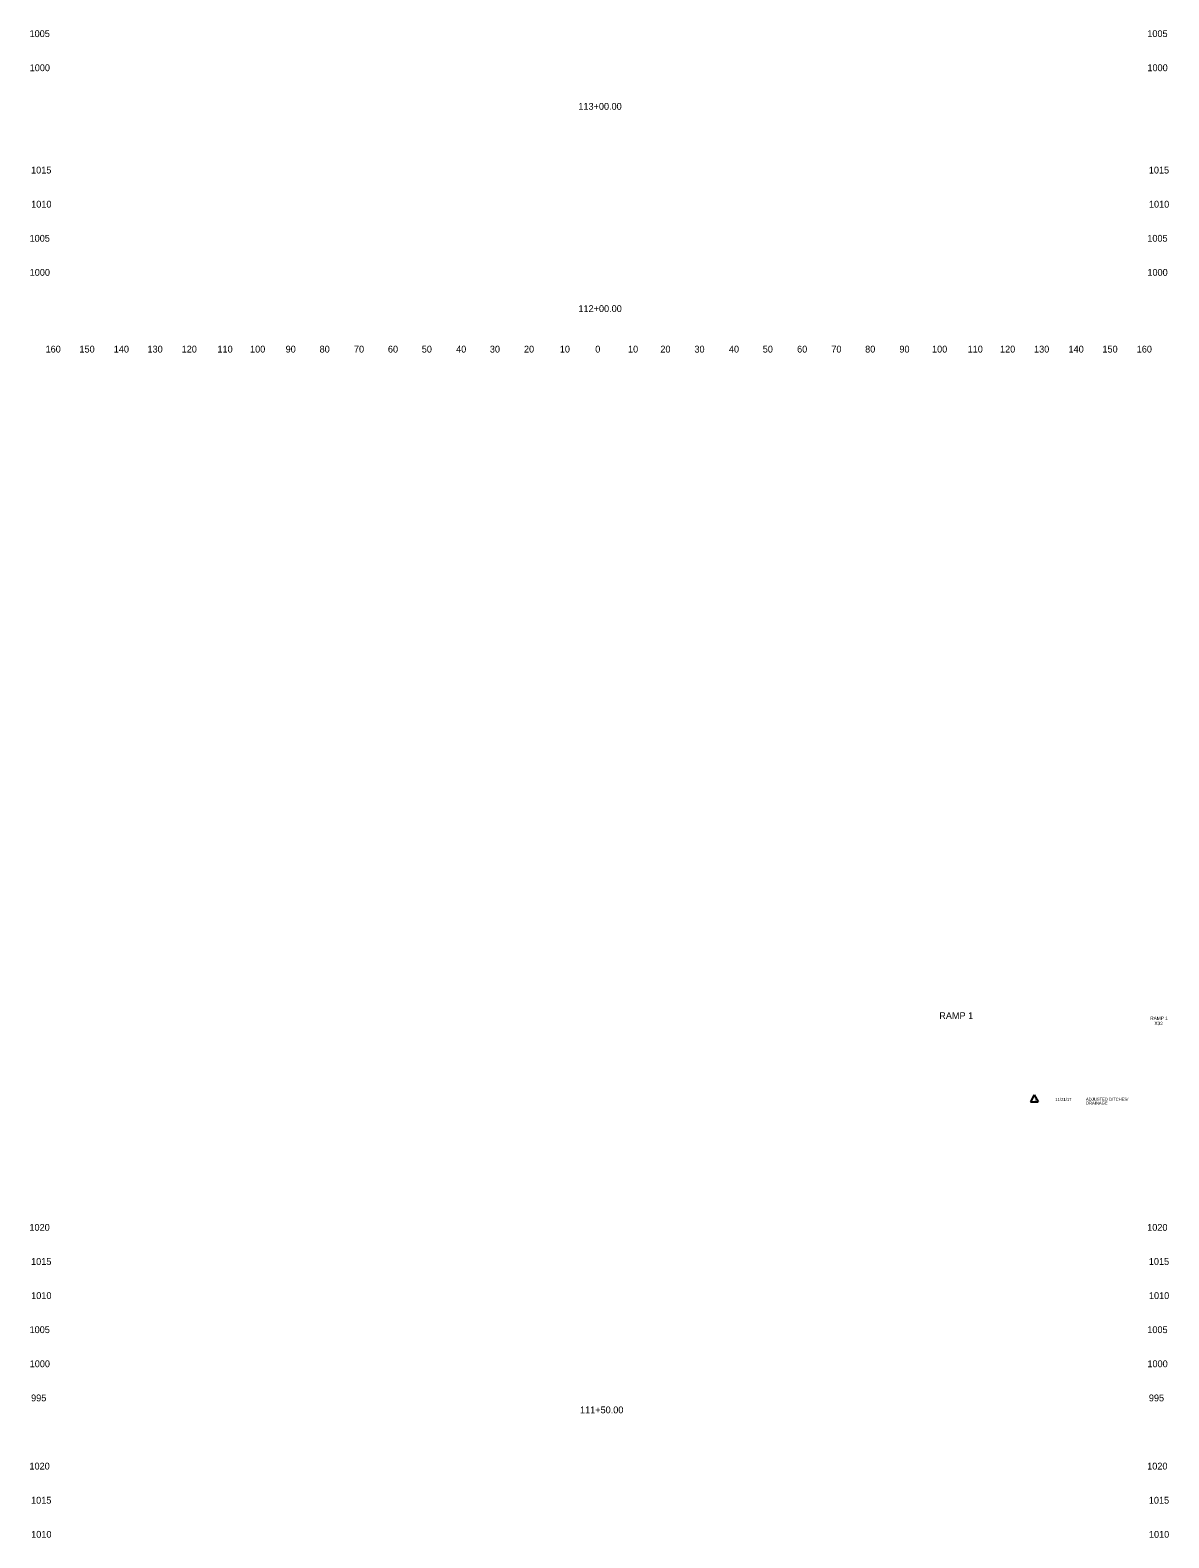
# Model space of a CAD drawing. Extents: x 4994 to 7869, y 4997 to 8804.
# Drawn here: x 6538.6 to 6872.5, y 5450 to 5892 of the extents above; entities that cross this region are included whole.
import ezdxf

# ---------------------------------------------------------------- set-up
doc = ezdxf.new("R2010")
doc.units = 0
for name, color, linetype in [('RD_SHT_ID', 7, 'Continuous'), ('RD_SHT_TX', 7, 'Continuous'), ('RD_XS_TX_Offset', 7, 'Continuous'), ('RD_XS_TX_Station', 7, 'Continuous')]:
    doc.layers.add(name, color=color, linetype=linetype)

msp = doc.modelspace()

# ---------------------------------------------------------------- linework, layer by layer
at = {"layer": 'RD_SHT_TX'}
for p, q in [((6833.05, 5579.83), (6831.91, 5577.8)), ((6833.05, 5579.83), (6834.19, 5577.8)), ((6831.91, 5577.8), (6834.19, 5577.8))]:
    msp.add_line(p, q, dxfattribs=at)

# ---------------------------------------------------------------- texts
at = {"layer": 'RD_SHT_ID'}
for s, height, p in [('RAMP 1', 2, (6805.19, 5602.06)), ('RAMP 1', 1, (6867.06, 5601.8)), ('X32', 1, (6868.29, 5600.3))]:
    msp.add_text(s, height=height, dxfattribs=at).set_placement(p)
at = {"layer": 'RD_SHT_TX'}
for s, p in [('1', (6833.05, 5578.13)), ('11/21/17', (6839.24, 5578.09)), ('ADJUSTED DITCHES/', (6848.22, 5578.12)), ('DRAINAGE', (6848.22, 5577.02))]:
    msp.add_text(s, height=0.88, dxfattribs=at).set_placement(p)
at = {"layer": 'RD_XS_TX_Offset'}
for s, p in [('1005', (6538.4, 5890)), ('1005', (6866.2, 5890)), ('1000', (6538.44, 5880)), ('1000', (6866.24, 5880)), ('1015', (6538.85, 5850)), ('1015', (6866.65, 5850)), ('1010', (6538.88, 5840)), ('1010', (6866.68, 5840)), ('1005', (6538.4, 5830)), ('1005', (6866.2, 5830)), ('1000', (6538.44, 5820)), ('1000', (6866.24, 5820)), ('160', (6543.1, 5797.5)), ('150', (6553.04, 5797.5)), ('140', (6563.1, 5797.5)), ('130', (6572.99, 5797.5)), ('120', (6583.01, 5797.5)), ('110', (6593.51, 5797.5)), ('100', (6603.07, 5797.5)), ('90', (6613.5, 5797.5)), ('80', (6623.46, 5797.5)), ('70', (6633.54, 5797.5)), ('60', (6643.5, 5797.5)), ('50', (6653.43, 5797.5)), ('40', (6663.5, 5797.5)), ('30', (6673.39, 5797.5)), ('20', (6683.4, 5797.5)), ('10', (6693.91, 5797.5)), ('0', (6704.3, 5797.5)), ('0', (6704.3, 5797.5)), ('10', (6713.91, 5797.5)), ('20', (6723.4, 5797.5)), ('30', (6733.39, 5797.5)), ('40', (6743.5, 5797.5)), ('50', (6753.43, 5797.5)), ('60', (6763.5, 5797.5)), ('70', (6773.54, 5797.5)), ('80', (6783.46, 5797.5)), ('90', (6793.5, 5797.5)), ('100', (6803.07, 5797.5)), ('110', (6813.51, 5797.5)), ('120', (6823.01, 5797.5)), ('130', (6832.99, 5797.5)), ('140', (6843.1, 5797.5)), ('150', (6853.04, 5797.5)), ('160', (6863.1, 5797.5)), ('1020', (6538.37, 5540)), ('1020', (6866.17, 5540)), ('1015', (6538.85, 5530)), ('1015', (6866.65, 5530)), ('1010', (6538.88, 5520)), ('1010', (6866.68, 5520)), ('1005', (6538.4, 5510)), ('1005', (6866.2, 5510)), ('1000', (6538.44, 5500)), ('1000', (6866.24, 5500)), ('995', (6538.86, 5490)), ('995', (6866.66, 5490)), ('1020', (6538.37, 5470)), ('1020', (6866.17, 5470)), ('1015', (6538.85, 5460)), ('1015', (6866.65, 5460)), ('1010', (6538.88, 5450)), ('1010', (6866.68, 5450))]:
    msp.add_text(s, height=2, dxfattribs=at).set_placement(p)
at = {"layer": 'RD_XS_TX_Station'}
for s, p in [('113+00.00', (6699.35, 5868.69)), ('112+00.00', (6699.37, 5809.39)), ('111+50.00', (6699.84, 5486.49))]:
    msp.add_text(s, height=2, dxfattribs=at).set_placement(p)

doc.saveas('drawing.dxf')
